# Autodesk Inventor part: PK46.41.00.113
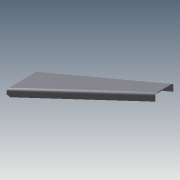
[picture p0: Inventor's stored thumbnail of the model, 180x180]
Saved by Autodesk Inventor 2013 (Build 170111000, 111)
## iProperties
Created: 2005-07
Part Number: PK46.41.00.113
Material: Steel, Mild
Document SubType Name: Листовой материал
Designer: PVitaliy
Manufacturer: Standard
Standards Organization: Custom
Density: 7.86 g/cm^3
Sheet Metal Rule: По умолчанию
Author: PVitaliy
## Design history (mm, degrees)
node "Грань1"
node "Фланец1"
node "Фланец2"
feature "Угловая фаска1" dims "d23" = 10, "d24" = 6, angle "d25" = 45 deg
body "Solid1"
sketch "Эскиз2"
  geometry: L1 (0, 0)-(0, 120); L2 (0, 120)-(300, 340); L3 (300, 340)-(300, 270); L4 (300, 270)-(0, 0)
  constraints: 8 end point, 2 vertical, 1 other
  dimensions: "d0" = 120 distance of L1.start L1.end; "d1" = 70 distance of L2.end L3.end; "d2" = 340 vertical distance of L2.end L1.start; "d3" = 300 distance between parallel lines of L3 L1
feature "Плакирование1" dims "Толщина" = 3
sketch "Эскиз3"
  geometry: L1 through (-186.011, 0) direction (-1, 0); L2 (-372.022, 0)-(-372.022, -24); L3 (-372.022, -24)-(0, -24); L4 through (0, -12) direction (-6.16e-33, 1)
  constraints: 6 end point, 1 horizontal, 1 perpendicular, 1 vertical
feature "Плакирование2" dims "d5" = 3 (= Ширина_просечки), "d7" = 6 (= Минимальный_остаток), "d9" = 24, "d10" = 90 deg, "d11" = 5 (= Радиус_гибки), "Толщина" = 3
feature "Изгиб1" dims "d5" = 3 (= Ширина_просечки), "d6" = 1.5 (= Глубина_просечки), "d7" = 6 (= Минимальный_остаток), "d8" = 5 (= Радиус_гибки), "d9" = 24, "d10" = 90 deg, "d11" = 5 (= Радиус_гибки), "Толщина" = 3, "Зазор_стыка" = 0.01
sketch "Эскиз4"
  geometry: L1 through (-201.804, 0) direction (-1, 4.89e-33); L2 (-403.609, 0)-(-403.609, -24); L3 (-403.609, -24)-(0, -24); L4 through (0, -12) direction (0, 1)
  constraints: 6 end point, 1 horizontal, 1 perpendicular, 1 vertical
feature "Плакирование3" dims "d12" = 3 (= Ширина_просечки), "d14" = 6 (= Минимальный_остаток), "d16" = 24, "d17" = 90 deg, "d18" = 5 (= Радиус_гибки), "Толщина" = 3
feature "Изгиб2" dims "d12" = 3 (= Ширина_просечки), "d13" = 1.5 (= Глубина_просечки), "d14" = 6 (= Минимальный_остаток), "d15" = 5 (= Радиус_гибки), "d16" = 24, "d17" = 90 deg, "d18" = 5 (= Радиус_гибки), "Толщина" = 3, "Зазор_стыка" = 0.01
other parameters: "Радиус_гибки" = 5, "Ширина_просечки" = 3 (= Толщина), "Глубина_просечки" = 1.5 (= 0.5 x Толщина), "Размер_высечки" = 12 (= 4 x Толщина), "Минимальный_остаток" = 6 (= 2 x Толщина), "Радиус_перехода" = 5 (= Радиус_гибки), "d4" = 5 (= Радиус_гибки), "JacobiRadiusSize" = 3 (= Толщина), "GapSize" = 3 (= Толщина)
